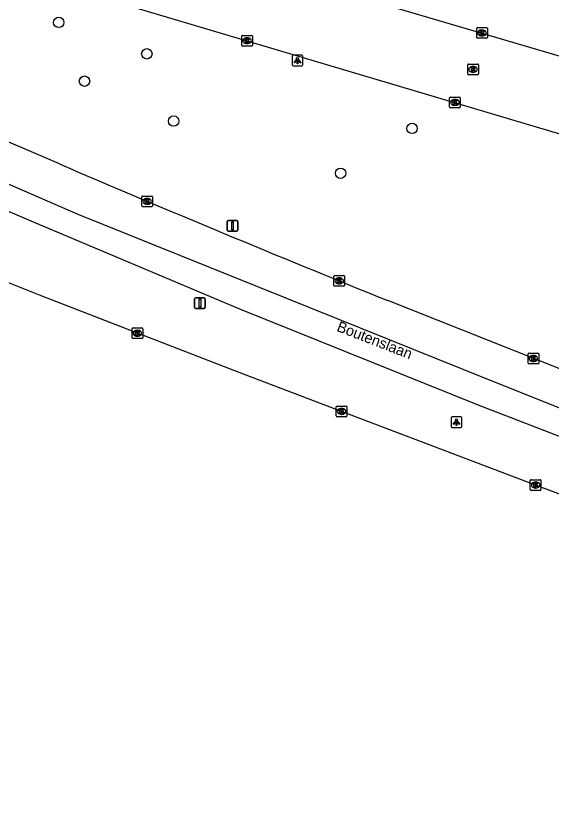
# Model space of a CAD drawing. Extents: x 160356 to 161355, y 381727 to 382845.
# Drawn here: x 160715 to 160765.3, y 381820.9 to 381896 of the extents above; entities that cross this region are included whole.
import ezdxf

# ---------------------------------------------------------------- set-up
doc = ezdxf.new("R2010")
doc.units = 0
for name, color, linetype in [('IMGEO_Boom', 7, 'Continuous'), ('IMGEO_Kolk', 7, 'Continuous'), ('IMGEO_Lichtpunt', 7, 'Continuous'), ('IMGEO_Openbare_ruimte_label', 7, 'Continuous'), ('IMGEO_Rijbaan_lokaal_open', 7, 'Continuous'), ('IMGEO_Rijbaan_regionaal_gesloten', 7, 'Continuous'), ('IMGEO_Rioolput', 7, 'Continuous'), ('IMGEO_Verkeersbordpaal', 7, 'Continuous')]:
    doc.layers.add(name, color=color, linetype=linetype)

msp = doc.modelspace()

# ---------------------------------------------------------------- linework, layer by layer
at = {"layer": 'IMGEO_Boom'}
for centre in [(160719.052, 381895.431), (160727.316, 381892.476), (160721.465, 381889.909), (160729.831, 381886.168), (160752.208, 381885.478), (160745.495, 381881.261)]:
    msp.add_circle(centre, 0.489, dxfattribs=at)
at = {"layer": 'IMGEO_Kolk'}
for p, q in [((160758.269, 381894.018), (160758.269, 381894.87)), ((160758.344, 381894.944), (160759.196, 381894.944)), ((160758.757, 381894.724), (160758.782, 381894.724)), ((160759.27, 381894.87), (160759.27, 381894.018)), ((160736.22, 381893.288), (160736.22, 381894.14)), ((160736.295, 381894.214), (160737.147, 381894.214)), ((160736.708, 381893.994), (160736.733, 381893.994)), ((160737.221, 381894.14), (160737.221, 381893.288)), ((160759.196, 381893.944), (160758.344, 381893.944)), ((160758.78, 381894.164), (160758.755, 381894.164)), ((160737.147, 381893.214), (160736.295, 381893.214)), ((160736.731, 381893.434), (160736.706, 381893.434)), ((160755.807, 381888.414), (160756.659, 381888.414)), ((160755.732, 381887.488), (160755.732, 381888.34)), ((160756.22, 381888.194), (160756.245, 381888.194)), ((160756.733, 381888.34), (160756.733, 381887.488)), ((160756.659, 381887.414), (160755.807, 381887.414)), ((160756.243, 381887.634), (160756.218, 381887.634)), ((160726.847, 381878.194), (160726.847, 381879.046)), ((160726.922, 381879.12), (160727.774, 381879.12)), ((160727.335, 381878.9), (160727.36, 381878.9)), ((160727.848, 381879.046), (160727.848, 381878.194)), ((160727.774, 381878.12), (160726.922, 381878.12)), ((160727.358, 381878.34), (160727.333, 381878.34)), ((160744.87, 381870.737), (160744.87, 381871.589)), ((160744.945, 381871.663), (160745.797, 381871.663)), ((160745.358, 381871.443), (160745.383, 381871.443)), ((160745.871, 381871.589), (160745.871, 381870.737)), ((160745.797, 381870.663), (160744.945, 381870.663)), ((160745.381, 381870.883), (160745.356, 381870.883)), ((160725.929, 381865.815), (160725.929, 381866.667)), ((160726.004, 381866.741), (160726.856, 381866.741)), ((160726.93, 381866.667), (160726.93, 381865.815)), ((160726.44, 381865.961), (160726.415, 381865.961)), ((160726.417, 381866.521), (160726.442, 381866.521)), ((160726.856, 381865.741), (160726.004, 381865.741)), ((160763.087, 381863.443), (160763.087, 381864.295)), ((160763.162, 381864.369), (160764.014, 381864.369)), ((160763.575, 381864.149), (160763.6, 381864.149)), ((160764.088, 381864.295), (160764.088, 381863.443)), ((160764.014, 381863.369), (160763.162, 381863.369)), ((160763.598, 381863.589), (160763.573, 381863.589)), ((160745.089, 381858.472), (160745.089, 381859.324)), ((160745.164, 381859.398), (160746.016, 381859.398)), ((160745.577, 381859.178), (160745.602, 381859.178)), ((160746.09, 381859.324), (160746.09, 381858.472)), ((160746.016, 381858.398), (160745.164, 381858.398)), ((160745.6, 381858.618), (160745.575, 381858.618)), ((160763.297, 381851.559), (160763.297, 381852.411)), ((160763.372, 381852.485), (160764.224, 381852.485)), ((160764.298, 381852.411), (160764.298, 381851.559)), ((160763.808, 381851.705), (160763.783, 381851.705)), ((160763.785, 381852.265), (160763.81, 381852.265)), ((160764.224, 381851.485), (160763.372, 381851.485))]:
    msp.add_line(p, q, dxfattribs=at)
for points in [[(160758.269, 381894.018), (160758.269, 381894.87)], [(160758.344, 381894.944), (160759.196, 381894.944)], [(160758.59, 381894.644), (160758.713, 381894.644), (160758.713, 381894.493), (160758.843, 381894.644), (160759.007, 381894.644), (160758.861, 381894.493), (160759.014, 381894.244), (160758.862, 381894.244), (160758.777, 381894.408), (160758.713, 381894.341), (160758.713, 381894.244), (160758.59, 381894.244), (160758.59, 381894.644)], [(160759.27, 381894.87), (160759.27, 381894.018)], [(160736.22, 381893.288), (160736.22, 381894.14)], [(160736.295, 381894.214), (160737.147, 381894.214)], [(160736.541, 381893.914), (160736.664, 381893.914), (160736.664, 381893.763), (160736.794, 381893.914), (160736.958, 381893.914), (160736.812, 381893.763), (160736.965, 381893.514), (160736.813, 381893.514), (160736.728, 381893.678), (160736.664, 381893.611), (160736.664, 381893.514), (160736.541, 381893.514), (160736.541, 381893.914)], [(160737.221, 381894.14), (160737.221, 381893.288)], [(160759.196, 381893.944), (160758.344, 381893.944)], [(160737.147, 381893.214), (160736.295, 381893.214)], [(160755.807, 381888.414), (160756.659, 381888.414)], [(160755.732, 381887.488), (160755.732, 381888.34)], [(160756.053, 381888.114), (160756.176, 381888.114), (160756.176, 381887.963), (160756.306, 381888.114), (160756.47, 381888.114), (160756.324, 381887.963), (160756.477, 381887.714), (160756.325, 381887.714), (160756.24, 381887.878), (160756.176, 381887.811), (160756.176, 381887.714), (160756.053, 381887.714), (160756.053, 381888.114)], [(160756.733, 381888.34), (160756.733, 381887.488)], [(160756.659, 381887.414), (160755.807, 381887.414)], [(160726.847, 381878.194), (160726.847, 381879.046)], [(160726.922, 381879.12), (160727.774, 381879.12)], [(160727.168, 381878.82), (160727.291, 381878.82), (160727.291, 381878.669), (160727.421, 381878.82), (160727.585, 381878.82), (160727.439, 381878.669), (160727.592, 381878.42), (160727.44, 381878.42), (160727.355, 381878.584), (160727.291, 381878.517), (160727.291, 381878.42), (160727.168, 381878.42), (160727.168, 381878.82)], [(160727.848, 381879.046), (160727.848, 381878.194)], [(160727.774, 381878.12), (160726.922, 381878.12)], [(160744.87, 381870.737), (160744.87, 381871.589)], [(160744.945, 381871.663), (160745.797, 381871.663)], [(160745.191, 381871.363), (160745.314, 381871.363), (160745.314, 381871.212), (160745.444, 381871.363), (160745.608, 381871.363), (160745.462, 381871.212), (160745.615, 381870.963), (160745.463, 381870.963), (160745.378, 381871.127), (160745.314, 381871.06), (160745.314, 381870.963), (160745.191, 381870.963), (160745.191, 381871.363)], [(160745.871, 381871.589), (160745.871, 381870.737)], [(160745.797, 381870.663), (160744.945, 381870.663)], [(160725.929, 381865.815), (160725.929, 381866.667)], [(160726.004, 381866.741), (160726.856, 381866.741)], [(160726.93, 381866.667), (160726.93, 381865.815)], [(160726.25, 381866.441), (160726.373, 381866.441), (160726.373, 381866.29), (160726.503, 381866.441), (160726.667, 381866.441), (160726.521, 381866.29), (160726.674, 381866.041), (160726.522, 381866.041), (160726.437, 381866.205), (160726.373, 381866.138), (160726.373, 381866.041), (160726.25, 381866.041), (160726.25, 381866.441)], [(160726.856, 381865.741), (160726.004, 381865.741)], [(160763.087, 381863.443), (160763.087, 381864.295)], [(160763.162, 381864.369), (160764.014, 381864.369)], [(160763.408, 381864.069), (160763.531, 381864.069), (160763.531, 381863.918), (160763.661, 381864.069), (160763.825, 381864.069), (160763.679, 381863.918), (160763.832, 381863.669), (160763.68, 381863.669), (160763.595, 381863.833), (160763.531, 381863.766), (160763.531, 381863.669), (160763.408, 381863.669), (160763.408, 381864.069)], [(160764.088, 381864.295), (160764.088, 381863.443)], [(160764.014, 381863.369), (160763.162, 381863.369)], [(160745.089, 381858.472), (160745.089, 381859.324)], [(160745.164, 381859.398), (160746.016, 381859.398)], [(160746.09, 381859.324), (160746.09, 381858.472)], [(160746.016, 381858.398), (160745.164, 381858.398)], [(160745.41, 381859.098), (160745.533, 381859.098), (160745.533, 381858.947), (160745.663, 381859.098), (160745.827, 381859.098), (160745.681, 381858.947), (160745.834, 381858.698), (160745.682, 381858.698), (160745.597, 381858.862), (160745.533, 381858.795), (160745.533, 381858.698), (160745.41, 381858.698), (160745.41, 381859.098)], [(160763.297, 381851.559), (160763.297, 381852.411)], [(160763.372, 381852.485), (160764.224, 381852.485)], [(160764.298, 381852.411), (160764.298, 381851.559)], [(160763.618, 381852.185), (160763.741, 381852.185), (160763.741, 381852.034), (160763.871, 381852.185), (160764.035, 381852.185), (160763.889, 381852.034), (160764.042, 381851.785), (160763.89, 381851.785), (160763.805, 381851.949), (160763.741, 381851.882), (160763.741, 381851.785), (160763.618, 381851.785), (160763.618, 381852.185)], [(160764.224, 381851.485), (160763.372, 381851.485)]]:
    msp.add_lwpolyline(points, dxfattribs=at)
for centre, start, end in [((160758.346, 381894.868), 91.55205, 178.44795), ((160758.346, 381894.868), 91.55205, 178.44795), ((160759.194, 381894.868), 1.55205, 88.44795), ((160759.194, 381894.868), 1.55205, 88.44795), ((160736.297, 381894.138), 91.55205, 178.44795), ((160736.297, 381894.138), 91.55205, 178.44795), ((160737.145, 381894.138), 1.55205, 88.44795), ((160737.145, 381894.138), 1.55205, 88.44795), ((160758.346, 381894.02), 181.55205, 268.44795), ((160758.346, 381894.02), 181.55205, 268.44795), ((160759.194, 381894.02), 271.55205, 358.44795), ((160759.194, 381894.02), 271.55205, 358.44795), ((160736.297, 381893.29), 181.55205, 268.44795), ((160736.297, 381893.29), 181.55205, 268.44795), ((160737.145, 381893.29), 271.55205, 358.44795), ((160737.145, 381893.29), 271.55205, 358.44795), ((160755.809, 381888.338), 91.55205, 178.44795), ((160755.809, 381888.338), 91.55205, 178.44795), ((160756.657, 381888.338), 1.55205, 88.44795), ((160756.657, 381888.338), 1.55205, 88.44795), ((160755.809, 381887.49), 181.55205, 268.44795), ((160755.809, 381887.49), 181.55205, 268.44795), ((160756.657, 381887.49), 271.55205, 358.44795), ((160756.657, 381887.49), 271.55205, 358.44795), ((160726.924, 381879.044), 91.55205, 178.44795), ((160726.924, 381879.044), 91.55205, 178.44795), ((160727.772, 381879.044), 1.55205, 88.44795), ((160727.772, 381879.044), 1.55205, 88.44795), ((160726.924, 381878.196), 181.55205, 268.44795), ((160726.924, 381878.196), 181.55205, 268.44795), ((160727.772, 381878.196), 271.55205, 358.44795), ((160727.772, 381878.196), 271.55205, 358.44795), ((160744.947, 381871.587), 91.55205, 178.44795), ((160744.947, 381871.587), 91.55205, 178.44795), ((160745.795, 381871.587), 1.55205, 88.44795), ((160745.795, 381871.587), 1.55205, 88.44795), ((160744.947, 381870.739), 181.55205, 268.44795), ((160744.947, 381870.739), 181.55205, 268.44795), ((160745.795, 381870.739), 271.55205, 358.44795), ((160745.795, 381870.739), 271.55205, 358.44795), ((160726.006, 381866.665), 91.55205, 178.44795), ((160726.006, 381866.665), 91.55205, 178.44795), ((160726.854, 381866.665), 1.55205, 88.44795), ((160726.854, 381866.665), 1.55205, 88.44795), ((160726.006, 381865.817), 181.55205, 268.44795), ((160726.006, 381865.817), 181.55205, 268.44795), ((160726.854, 381865.817), 271.55205, 358.44795), ((160726.854, 381865.817), 271.55205, 358.44795), ((160763.164, 381864.293), 91.55205, 178.44795), ((160763.164, 381864.293), 91.55205, 178.44795), ((160764.012, 381864.293), 1.55205, 88.44795), ((160764.012, 381864.293), 1.55205, 88.44795), ((160763.164, 381863.445), 181.55205, 268.44795), ((160763.164, 381863.445), 181.55205, 268.44795), ((160764.012, 381863.445), 271.55205, 358.44795), ((160764.012, 381863.445), 271.55205, 358.44795), ((160745.166, 381859.322), 91.55205, 178.44795), ((160745.166, 381859.322), 91.55205, 178.44795), ((160746.014, 381859.322), 1.55205, 88.44795), ((160746.014, 381859.322), 1.55205, 88.44795), ((160745.166, 381858.474), 181.55205, 268.44795), ((160745.166, 381858.474), 181.55205, 268.44795), ((160746.014, 381858.474), 271.55205, 358.44795), ((160746.014, 381858.474), 271.55205, 358.44795), ((160763.374, 381852.409), 91.55205, 178.44795), ((160763.374, 381852.409), 91.55205, 178.44795), ((160764.222, 381852.409), 1.55205, 88.44795), ((160764.222, 381852.409), 1.55205, 88.44795), ((160763.374, 381851.561), 181.55205, 268.44795), ((160763.374, 381851.561), 181.55205, 268.44795), ((160764.222, 381851.561), 271.55205, 358.44795), ((160764.222, 381851.561), 271.55205, 358.44795)]:
    msp.add_arc(centre, 0.0765, start, end, dxfattribs=at)
for centre, major_axis, ratio, start_param, end_param in [((160758.756, 381894.444), (-0.387, 0.002), 0.722429, 4.712389, 7.853982), ((160758.781, 381894.444), (-0.39, 0.002), 0.717154, 1.570796, 4.712389), ((160736.707, 381893.714), (-0.387, 0.002), 0.722429, 4.712389, 7.853982), ((160736.732, 381893.714), (-0.39, 0.002), 0.717154, 1.570796, 4.712389), ((160756.219, 381887.914), (-0.387, 0.002), 0.722429, 4.712389, 7.853982), ((160756.244, 381887.914), (-0.39, 0.002), 0.717154, 1.570796, 4.712389), ((160727.334, 381878.62), (-0.387, 0.002), 0.722429, 4.712389, 7.853982), ((160727.359, 381878.62), (-0.39, 0.002), 0.717154, 1.570796, 4.712389), ((160745.357, 381871.163), (-0.387, 0.002), 0.722429, 4.712389, 7.853982), ((160745.382, 381871.163), (-0.39, 0.002), 0.717154, 1.570796, 4.712389), ((160726.416, 381866.241), (-0.387, 0.002), 0.722429, 4.712389, 7.853982), ((160726.441, 381866.241), (-0.39, 0.002), 0.717154, 1.570796, 4.712389), ((160763.574, 381863.869), (-0.387, 0.002), 0.722429, 4.712389, 7.853982), ((160763.599, 381863.869), (-0.39, 0.002), 0.717154, 1.570796, 4.712389), ((160745.576, 381858.898), (-0.387, 0.002), 0.722429, 4.712389, 7.853982), ((160745.601, 381858.898), (-0.39, 0.002), 0.717154, 1.570796, 4.712389), ((160763.784, 381851.985), (-0.387, 0.002), 0.722429, 4.712389, 7.853982), ((160763.809, 381851.985), (-0.39, 0.002), 0.717154, 1.570796, 4.712389)]:
    msp.add_ellipse(centre, major_axis=major_axis, ratio=ratio, start_param=start_param, end_param=end_param, dxfattribs=at)
at = {"layer": 'IMGEO_Lichtpunt'}
for p, q in [((160740.947, 381892.244), (160740.947, 381891.437)), ((160740.947, 381892.244), (160740.947, 381891.437)), ((160741.849, 381892.339), (160741.041, 381892.339)), ((160741.849, 381892.339), (160741.041, 381892.339)), ((160741.943, 381891.437), (160741.943, 381892.244)), ((160741.943, 381891.437), (160741.943, 381892.244)), ((160741.041, 381891.343), (160741.849, 381891.343)), ((160741.041, 381891.343), (160741.849, 381891.343)), ((160756.782, 381858.391), (160755.974, 381858.391)), ((160756.782, 381858.391), (160755.974, 381858.391)), ((160755.88, 381858.296), (160755.88, 381857.489)), ((160755.88, 381858.296), (160755.88, 381857.489)), ((160756.876, 381857.489), (160756.876, 381858.296)), ((160756.876, 381857.489), (160756.876, 381858.296)), ((160755.974, 381857.395), (160756.782, 381857.395)), ((160755.974, 381857.395), (160756.782, 381857.395))]:
    msp.add_line(p, q, dxfattribs=at)
for points in [[(160741.321, 381891.908), (160741.36, 381891.88), (160741.172, 381891.618), (160741.134, 381891.645), (160741.321, 381891.908)], [(160741.423, 381891.86), (160741.47, 381891.86), (160741.47, 381891.538), (160741.423, 381891.538), (160741.423, 381891.86)], [(160741.533, 381891.88), (160741.571, 381891.907), (160741.758, 381891.645), (160741.719, 381891.617), (160741.533, 381891.88)], [(160756.254, 381857.96), (160756.293, 381857.932), (160756.105, 381857.67), (160756.067, 381857.697), (160756.254, 381857.96)], [(160756.356, 381857.912), (160756.403, 381857.912), (160756.403, 381857.59), (160756.356, 381857.59), (160756.356, 381857.912)], [(160756.466, 381857.932), (160756.504, 381857.959), (160756.691, 381857.697), (160756.652, 381857.669), (160756.466, 381857.932)]]:
    msp.add_lwpolyline(points, dxfattribs=at)
for centre in [(160741.446, 381892.042), (160756.379, 381858.094)]:
    msp.add_circle(centre, 0.0994, dxfattribs=at)
for centre, start, end in [((160741.041, 381892.244), 90, 180), ((160741.041, 381892.244), 90, 180), ((160741.849, 381892.244), 0, 90), ((160741.849, 381892.244), 0, 90), ((160741.041, 381891.437), 180, 270), ((160741.041, 381891.437), 180, 270), ((160741.849, 381891.437), 270, 0), ((160741.849, 381891.437), 270, 360), ((160755.974, 381858.296), 90, 180), ((160755.974, 381858.296), 90, 180), ((160756.782, 381858.296), 0, 90), ((160756.782, 381858.296), 0, 90), ((160755.974, 381857.489), 180, 270), ((160755.974, 381857.489), 180, 270), ((160756.782, 381857.489), 270, 0), ((160756.782, 381857.489), 270, 360)]:
    msp.add_arc(centre, 0.0946, start, end, dxfattribs=at)
at = {"layer": 'IMGEO_Rijbaan_lokaal_open'}
for points in [[(160679.993, 381917.834), (160691.804, 381914.329), (160703.301, 381910.962), (160713.383, 381907.976), (160724.219, 381904.806), (160729.348, 381903.194), (160740.094, 381899.948), (160744.941, 381898.519), (160820.691, 381876.187), (160826.955, 381874.36)], [(160824.304, 381867.688), (160819.275, 381869.125), (160815.643, 381870.203), (160710.934, 381901.384), (160677.174, 381911.473)]]:
    msp.add_lwpolyline(points, dxfattribs=at)
at = {"layer": 'IMGEO_Rijbaan_regionaal_gesloten'}
for points in [[(160719.115, 381882.137), (160697.175, 381891.554), (160673.041, 381902.206)], [(160873.607, 381820.906), (160850.039, 381828.315), (160815.758, 381840.347), (160785.928, 381851.241), (160759.412, 381861.851), (160720.869, 381877.388), (160685.357, 381892.83), (160671.637, 381899.009)], [(160670.634, 381896.725), (160699.138, 381884.208), (160716.646, 381876.715), (160736.019, 381868.541), (160758.326, 381859.56), (160788.426, 381847.889), (160803.788, 381842.174), (160824.057, 381834.87), (160842.005, 381828.58)], [(160840.502, 381824.088), (160840.114, 381824.221), (160830.906, 381827.437), (160821.668, 381830.691), (160815.791, 381832.832), (160807.772, 381835.736), (160801.399, 381838.066), (160791.783, 381841.583), (160782.927, 381844.842), (160773.121, 381848.488), (160763.798, 381851.984), (160754.161, 381855.637), (160745.59, 381858.897), (160735.987, 381862.566), (160726.43, 381866.24), (160717.258, 381869.831), (160708.297, 381873.392), (160699.855, 381876.767), (160691.145, 381880.297), (160682.593, 381883.817), (160672.187, 381888.066), (160667.645, 381889.952)], [(160766.371, 381862.777), (160749.93, 381869.312)]]:
    msp.add_lwpolyline(points, dxfattribs=at)
msp.add_arc((161341.754, 383334.737), 1580.419, 246.798209, 248.008277, dxfattribs=at)
at = {"layer": 'IMGEO_Rioolput'}
for p, q in [((160757.427, 381890.594), (160757.427, 381891.446)), ((160757.502, 381891.52), (160758.354, 381891.52)), ((160758.428, 381891.446), (160758.428, 381890.594)), ((160757.938, 381890.74), (160757.913, 381890.74)), ((160757.915, 381891.3), (160757.94, 381891.3)), ((160758.354, 381890.52), (160757.502, 381890.52))]:
    msp.add_line(p, q, dxfattribs=at)
for points in [[(160757.427, 381890.594), (160757.427, 381891.446)], [(160757.502, 381891.52), (160758.354, 381891.52)], [(160758.428, 381891.446), (160758.428, 381890.594)], [(160758.016, 381891.218), (160757.764, 381891.22), (160757.764, 381890.82)], [(160757.764, 381890.82), (160757.888, 381890.82), (160757.888, 381890.982), (160757.899, 381890.982)], [(160757.942, 381891.139), (160757.888, 381891.139), (160757.888, 381891.058)], [(160757.888, 381891.058), (160757.94, 381891.058)], [(160757.946, 381890.953), (160758.017, 381890.82), (160758.157, 381890.82), (160758.092, 381890.946)], [(160758.354, 381890.52), (160757.502, 381890.52)]]:
    msp.add_lwpolyline(points, dxfattribs=at)
for centre, radius, start, end in [((160757.504, 381891.444), 0.0765, 91.55205, 178.44795), ((160757.504, 381891.444), 0.0765, 91.55205, 178.44795), ((160758.352, 381891.444), 0.0765, 1.55205, 88.44795), ((160758.352, 381891.444), 0.0765, 1.55205, 88.44795), ((160757.898, 381890.929), 0.0533, 26.02933, 88.69889), ((160757.924, 381891.247), 0.19, 274.7715, 282.96867), ((160757.948, 381891.043), 0.0964, 77.00612, 93.18647), ((160757.962, 381891.1), 0.0378, 276.66336, 79.67722), ((160758.015, 381891.108), 0.109, 350.36119, 89.41601), ((160758.013, 381891.108), 0.112, 277.58423, 350.98172), ((160757.997, 381890.893), 0.108, 29.51342, 73.79051), ((160757.504, 381890.596), 0.0765, 181.55205, 268.44795), ((160757.504, 381890.596), 0.0765, 181.55205, 268.44795), ((160758.352, 381890.596), 0.0765, 271.55205, 358.44795), ((160758.352, 381890.596), 0.0765, 271.55205, 358.44795)]:
    msp.add_arc(centre, radius, start, end, dxfattribs=at)
for centre, major_axis, ratio, start_param, end_param in [((160757.914, 381891.02), (-0.387, 0.002), 0.722429, 4.712389, 7.853982), ((160757.939, 381891.02), (-0.39, 0.002), 0.717154, 1.570796, 4.712389)]:
    msp.add_ellipse(centre, major_axis=major_axis, ratio=ratio, start_param=start_param, end_param=end_param, dxfattribs=at)
at = {"layer": 'IMGEO_Verkeersbordpaal'}
for p, q in [((160734.861, 381875.924), (160734.861, 381876.724)), ((160734.861, 381876.724), (160734.861, 381875.924)), ((160734.961, 381876.824), (160735.751, 381876.824)), ((160735.751, 381876.824), (160734.961, 381876.824)), ((160735.851, 381876.724), (160735.851, 381875.924)), ((160735.851, 381875.924), (160735.851, 381876.724)), ((160735.751, 381875.824), (160734.961, 381875.824)), ((160734.961, 381875.824), (160735.751, 381875.824)), ((160731.8, 381868.672), (160731.8, 381869.472)), ((160731.8, 381869.472), (160731.8, 381868.672)), ((160731.9, 381869.572), (160732.69, 381869.572)), ((160732.69, 381869.572), (160731.9, 381869.572)), ((160732.79, 381869.472), (160732.79, 381868.672)), ((160732.79, 381868.672), (160732.79, 381869.472)), ((160732.69, 381868.572), (160731.9, 381868.572)), ((160731.9, 381868.572), (160732.69, 381868.572))]:
    msp.add_line(p, q, dxfattribs=at)
for points in [[(160735.281, 381876.699), (160735.431, 381876.699), (160735.431, 381875.949), (160735.281, 381875.949), (160735.281, 381876.699)], [(160732.22, 381869.447), (160732.37, 381869.447), (160732.37, 381868.697), (160732.22, 381868.697), (160732.22, 381869.447)]]:
    msp.add_lwpolyline(points, dxfattribs=at)
for centre, start, end in [((160734.961, 381876.724), 90, 180), ((160734.961, 381876.724), 90, 180), ((160735.751, 381876.724), 0, 90), ((160735.751, 381876.724), 360, 90), ((160734.961, 381875.924), 180, 270), ((160734.961, 381875.924), 180, 270), ((160735.751, 381875.924), 270, 0), ((160735.751, 381875.924), 270, 0), ((160731.9, 381869.472), 90, 180), ((160731.9, 381869.472), 90, 180), ((160732.69, 381869.472), 0, 90), ((160732.69, 381869.472), 360, 90), ((160731.9, 381868.672), 180, 270), ((160731.9, 381868.672), 180, 270), ((160732.69, 381868.672), 270, 0), ((160732.69, 381868.672), 270, 0)]:
    msp.add_arc(centre, 0.1, start, end, dxfattribs=at)

# ---------------------------------------------------------------- texts
at = {"layer": 'IMGEO_Openbare_ruimte_label'}
msp.add_text('Boutenslaan', height=1, rotation=338.77323, dxfattribs=at).set_placement((160745.056, 381866.476))

doc.saveas('drawing.dxf')
